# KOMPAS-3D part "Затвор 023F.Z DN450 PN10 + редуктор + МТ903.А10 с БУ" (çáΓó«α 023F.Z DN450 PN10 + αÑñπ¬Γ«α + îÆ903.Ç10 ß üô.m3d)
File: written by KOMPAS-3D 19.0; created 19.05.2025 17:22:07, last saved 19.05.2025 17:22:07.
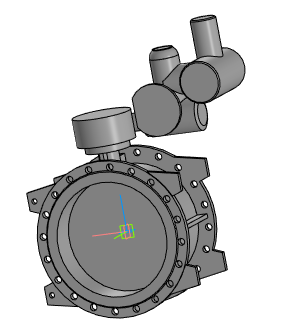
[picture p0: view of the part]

Document properties: Полное имя файла: Затвор 023F.Z DN450 PN10 + редуктор + МТ903.А10 с БУ.a3d

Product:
- Part/product: Затвор 023F.Z DN450 PN10 + редуктор + МТ903.А10 с БУ
    Масса: 350.774

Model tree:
1. Операция без истории:1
